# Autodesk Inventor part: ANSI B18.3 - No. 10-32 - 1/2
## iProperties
Comments: To add or edit properties for Autodesk Inventor files, use iProperties.
Created: 2005-02
Part Number: ANSI B18.3 - No. 10-32 - 1/2
Vendor: Autodesk Inc.
Document SubType Name: Modeling
Designer: John Blackburn
Material: Default
Description: Hexagon Socket Button Head Cap Screw
Standard: ANSI B18.3
Alert: To add or edit properties for Autodesk Inventor files, use iProperties.
Control State: 0
Master: False
Checked Out: False
Shininess: 64.0
Length Units: 11272
Angle Units: 11279
Time Units: 11290
Mass Units: 11286
Length Display Precision: 3
Angle Display Precision: 2
Compacted: True
EGR: 4
Classification: un/spsc 31161501
Density: 0.0
Volumn: 0.0
Area: 0.0
PropertySet Name: Model Information
Author: John Blackburn
Revision Number: 8
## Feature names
1. Body [Revolution]
2. Slot [Extrusion]
3. Fillet1
4. Chamfer1
